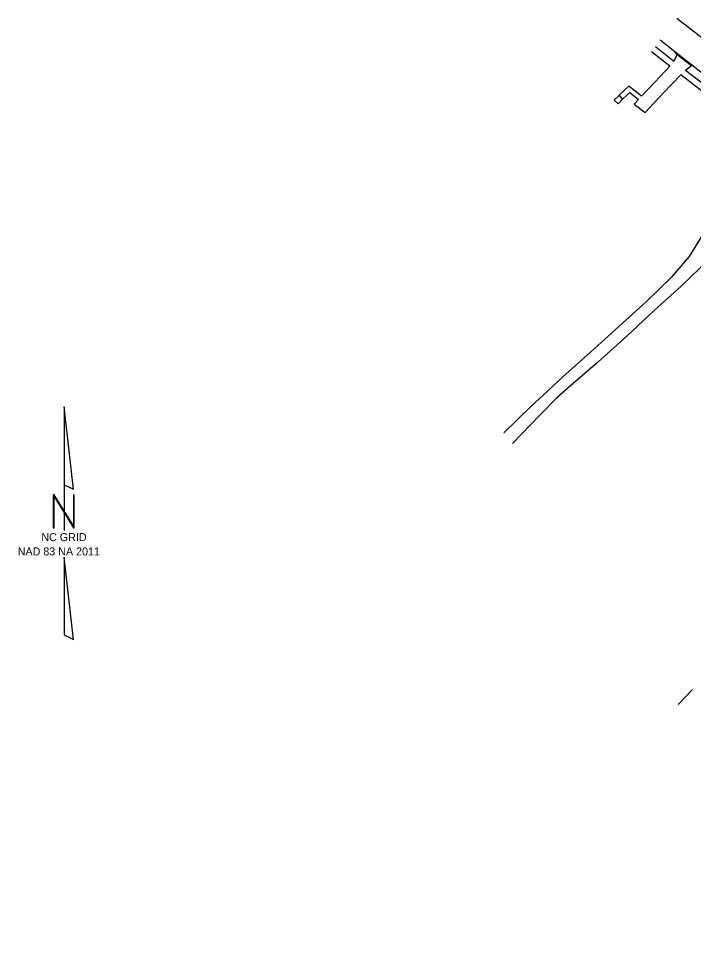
# Model space of a CAD drawing. Extents: x 1487693 to 1489338, y 497936 to 499734.
# Drawn here: x 1487836 to 1488342, y 498835 to 499533 of the extents above; entities that cross this region are included whole.
import ezdxf

# ---------------------------------------------------------------- set-up
doc = ezdxf.new("R2010")
doc.units = 0
for name, color, linetype in [('CTL North Arrow NAD 83 NA 2011 CELL', 7, 'Continuous'), ('Exist Roads EOP', 7, 'Continuous'), ('Exist Roads EOP Leader', 7, 'Continuous'), ('Exist Roads EOP Other', 7, 'Continuous'), ('Exist Roads Soil', 7, 'Continuous'), ('Prop Conc 4in Sidewalk', 7, 'Continuous')]:
    doc.layers.add(name, color=color, linetype=linetype)

msp = doc.modelspace()

# ---------------------------------------------------------------- linework, layer by layer
at = {"layer": 'CTL North Arrow NAD 83 NA 2011 CELL'}
msp.add_line((1487870.53, 499154.51), (1487870.53, 499154.51), dxfattribs=at)
for points in [[(1487870.38, 499241.8), (1487870.38, 499183.47), (1487877.25, 499180.04)], [(1487862.15, 499151.25), (1487862.84, 499151.25), (1487862.84, 499174.57), (1487877.25, 499151.25), (1487877.94, 499151.25), (1487877.94, 499175.94), (1487877.25, 499175.94), (1487877.25, 499152.61), (1487862.84, 499175.94), (1487862.15, 499175.94)], [(1487870.38, 499070.96), (1487877.25, 499067.55), (1487870.38, 499129.29)]]:
    msp.add_lwpolyline(points, close=True, dxfattribs=at)
msp.add_lwpolyline([(1487870.38, 499183.47), (1487870.38, 499149.17)], dxfattribs=at)
at = {"layer": 'Exist Roads EOP'}
for points in [[(1488492.34, 499402.94), (1488471.94, 499419.45), (1488453.17, 499434.37), (1488433.08, 499450.29), (1488413.86, 499465.57), (1488393.67, 499481.33), (1488375.11, 499496.41), (1488354.66, 499512.92), (1488329.29, 499532.68)], [(1488316.71, 499516.76), (1488322.91, 499511.87), (1488362.48, 499480.8), (1488401.61, 499449.34), (1488441.42, 499418.39), (1488480.75, 499387.27), (1488519.83, 499355.62), (1488558.68, 499324.4), (1488569.9, 499314.83), (1488572.03, 499312.84), (1488573.24, 499309.12), (1488574.89, 499302.98), (1488575.47, 499300.42), (1488574.66, 499299.19)], [(1488341.38, 499497.34), (1488340.75, 499497.68), (1488340.13, 499497.34), (1488329.43, 499505.59), (1488328.5, 499506.82), (1488327.67, 499508), (1488327.67, 499508)]]:
    msp.add_lwpolyline(points, dxfattribs=at)
at = {"layer": 'Exist Roads EOP Leader'}
msp.add_line((1488330.16, 499018.76), (1488340.84, 499030.06), dxfattribs=at)
at = {"layer": 'Exist Roads EOP Other'}
for p, q in [((1488313.29, 499511.68), (1488326.91, 499500.79)), ((1488323.87, 499496.97), (1488310.22, 499507.76)), ((1488285.93, 499475.15), (1488286.08, 499475.26)), ((1488288.63, 499472.44), (1488288.75, 499472.54))]:
    msp.add_line(p, q, dxfattribs=at)
for points in [[(1488326.91, 499500.79), (1488327.17, 499501.12), (1488328.25, 499503.32), (1488329.43, 499505.59)], [(1488323.87, 499496.97), (1488312.63, 499485.16), (1488302.68, 499474.61), (1488293.18, 499482.14), (1488286.08, 499475.26), (1488288.75, 499472.54), (1488294.09, 499477.29), (1488300.47, 499472.13), (1488297.19, 499468.66), (1488305.43, 499462.35), (1488318.84, 499476.61), (1488332.15, 499490.59)], [(1488340.13, 499497.34), (1488335.63, 499493.92)], [(1488413.28, 499425.48), (1488413.12, 499425.62), (1488399.44, 499436.7), (1488394.53, 499440.84), (1488374.27, 499457.47), (1488355.44, 499472.61), (1488332.15, 499490.59)], [(1488416.23, 499429.21), (1488415.8, 499429.57), (1488399.54, 499442.74), (1488397.09, 499444.8), (1488377.39, 499461.24), (1488358.9, 499476.14), (1488335.63, 499493.92)], [(1488288.63, 499472.44), (1488285.93, 499475.15), (1488282.39, 499471.54), (1488285.24, 499468.86), (1488288.63, 499472.44)]]:
    msp.add_lwpolyline(points, dxfattribs=at)
at = {"layer": 'Exist Roads Soil'}
for points in [[(1488399.44, 499436.7), (1488394.01, 499427.48), (1488386.68, 499415.56), (1488374.27, 499405.4), (1488357.79, 499389.37), (1488348.38, 499370.59), (1488338.38, 499354.49), (1488325, 499338.67), (1488306.42, 499320.8), (1488285.76, 499301.93), (1488264.48, 499282.79), (1488243.76, 499264.27), (1488232.24, 499253.63), (1488219.87, 499241.96), (1488199.63, 499222.34)], [(1488413.12, 499425.62), (1488407.76, 499417.42), (1488401.66, 499405.09), (1488388.96, 499392.92), (1488371.84, 499372.94), (1488360.19, 499360.84), (1488346.65, 499345.94), (1488332.26, 499332), (1488312.17, 499314.05), (1488291.91, 499295), (1488269.69, 499275.08), (1488249.66, 499257.48), (1488238.98, 499248.25), (1488226.24, 499235.41), (1488206.24, 499214.37)]]:
    msp.add_lwpolyline(points, dxfattribs=at)
at = {"layer": 'Prop Conc 4in Sidewalk'}
msp.add_arc((1487424.96, 499839.79), 1443.5, 305.25533, 321.11565, dxfattribs=at)

# ---------------------------------------------------------------- texts
at = {"layer": 'CTL North Arrow NAD 83 NA 2011 CELL'}
for s, p in [('NC GRID', (1487853.3, 499141.18)), ('NAD 83 NA 2011', (1487835.61, 499130.49))]:
    msp.add_text(s, height=6, dxfattribs=at).set_placement(p)

doc.saveas('drawing.dxf')
